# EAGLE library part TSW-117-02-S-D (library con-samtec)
THROUGH-HOLE .025" SQ POST HEADER Source: Samtec TSW.pdf
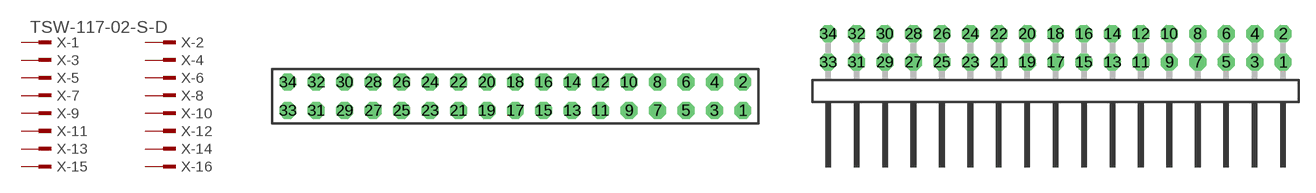
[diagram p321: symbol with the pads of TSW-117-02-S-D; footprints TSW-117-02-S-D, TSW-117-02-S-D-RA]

Designator prefix X; gates -1=MPINV -2=MPIN -3=MPIN -4=MPIN -5=MPIN -6=MPIN -7=MPIN -8=MPIN -9=MPIN -10=MPIN -11=MPIN -12=MPIN -13=MPIN -14=MPIN -15=MPIN -16=MPIN -17=MPIN -18=MPIN -19=MPIN -20=MPIN -21=MPIN -22=MPIN -23=MPIN -24=MPIN -25=MPIN -26=MPIN -27=MPIN -28=MPIN -29=MPIN -30=MPIN -31=MPIN -32=MPIN -33=MPIN -34=MPIN

## TSW-117-02-S-D (OC_FARNELL: unknown; OC_NEWARK: unknown)  [TSW-117-02-S-D]
1  -1:1  pas
2  -2:1  pas
3  -3:1  pas
4  -4:1  pas
5  -5:1  pas
6  -6:1  pas
7  -7:1  pas
8  -8:1  pas
9  -9:1  pas
10  -10:1  pas
11  -11:1  pas
12  -12:1  pas
13  -13:1  pas
14  -14:1  pas
15  -15:1  pas
16  -16:1  pas
17  -17:1  pas
18  -18:1  pas
19  -19:1  pas
20  -20:1  pas
21  -21:1  pas
22  -22:1  pas
23  -23:1  pas
24  -24:1  pas
25  -25:1  pas
26  -26:1  pas
27  -27:1  pas
28  -28:1  pas
29  -29:1  pas
30  -30:1  pas
31  -31:1  pas
32  -32:1  pas
33  -33:1  pas
34  -34:1  pas

## TSW-117-02-S-D-RA (OC_FARNELL: unknown; OC_NEWARK: unknown)  [TSW-117-02-S-D-RA]
Pads as for TSW-117-02-S-D

## Footprint TSW-117-02-S-D (pad centres in mm)
THROUGH-HOLE .025" SQ POST HEADER Source: Samtec TSW.pdf
drill 1 pad 1.5 octagon: 1 20.32,-1.27; 2 20.32,1.27; 3 17.78,-1.27; 4 17.78,1.27; 5 15.24,-1.27; 6 15.24,1.27; 7 12.7,-1.27; 8 12.7,1.27; 9 10.16,-1.27; 10 10.16,1.27; 11 7.62,-1.27; 12 7.62,1.27; 13 5.08,-1.27; 14 5.08,1.27; 15 2.54,-1.27; 16 2.54,1.27; 17 0,-1.27; 18 0,1.27; 19 -2.54,-1.27; 20 -2.54,1.27; 21 -5.08,-1.27; 22 -5.08,1.27; 23 -7.62,-1.27; 24 -7.62,1.27; 25 -10.16,-1.27; 26 -10.16,1.27; 27 -12.7,-1.27; 28 -12.7,1.27; 29 -15.24,-1.27; 30 -15.24,1.27; 31 -17.78,-1.27; 32 -17.78,1.27; 33 -20.32,-1.27; 34 -20.32,1.27

## Footprint TSW-117-02-S-D-RA (pad centres in mm)
THROUGH-HOLE .025" SQ POST HEADER Source: Samtec TSW.pdf
drill 1 pad 1.5 octagon: 1 20.32,1.524; 2 20.32,4.064; 3 17.78,1.524; 4 17.78,4.064; 5 15.24,1.524; 6 15.24,4.064; 7 12.7,1.524; 8 12.7,4.064; 9 10.16,1.524; 10 10.16,4.064; 11 7.62,1.524; 12 7.62,4.064; 13 5.08,1.524; 14 5.08,4.064; 15 2.54,1.524; 16 2.54,4.064; 17 0,1.524; 18 0,4.064; 19 -2.54,1.524; 20 -2.54,4.064; 21 -5.08,1.524; 22 -5.08,4.064; 23 -7.62,1.524; 24 -7.62,4.064; 25 -10.16,1.524; 26 -10.16,4.064; 27 -12.7,1.524; 28 -12.7,4.064; 29 -15.24,1.524; 30 -15.24,4.064; 31 -17.78,1.524; 32 -17.78,4.064; 33 -20.32,1.524; 34 -20.32,4.064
